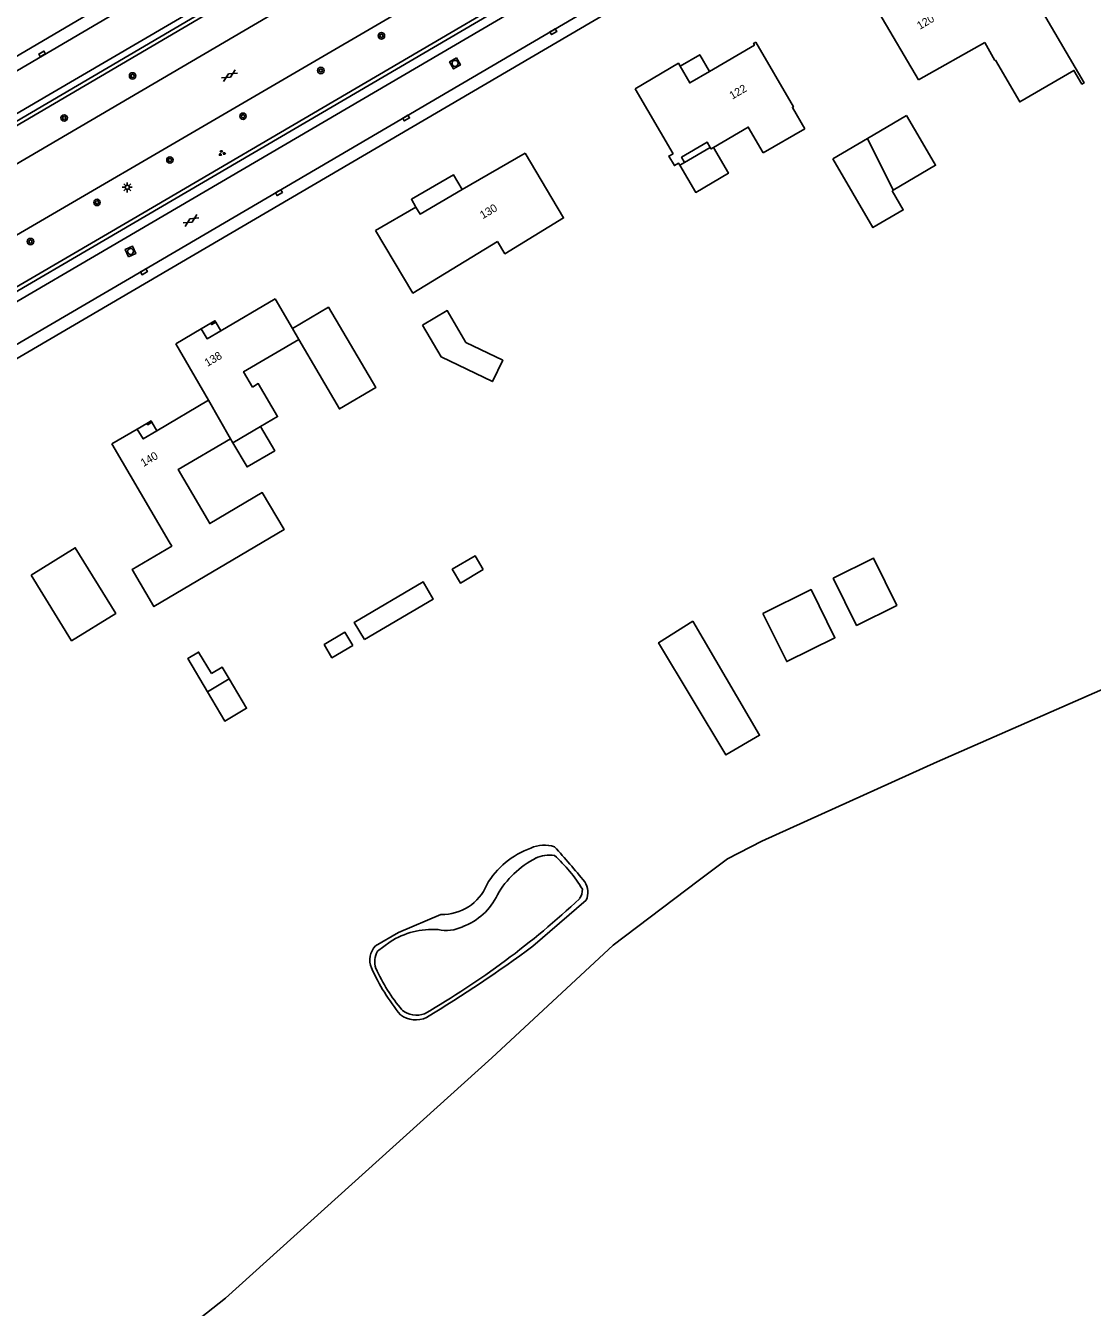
# Model space of a CAD drawing. Extents: x 135999 to 138000, y 396000 to 398501.
# Drawn here: x 136187.2 to 136320.6, y 397354.4 to 397514.6 of the extents above; entities that cross this region are included whole.
import ezdxf

# ---------------------------------------------------------------- set-up
doc = ezdxf.new("R2010")
doc.units = 0
for name, color, linetype in [('gg-afsc-draadraster', 7, 'Continuous'), ('gg-afsc-lijn draadraster', 7, 'Continuous'), ('gg-anno-huisnummerreeks BGT', 7, 'Continuous'), ('gg-bbg-bijgebouw', 7, 'Continuous'), ('gg-bbg-gedigitaliseerde bebouwing', 7, 'Continuous'), ('gg-bbg-gedigitaliseerde bebouwing onder overbouw', 7, 'Continuous'), ('gg-bbg-gedigitaliseerde bijgebouw', 7, 'Continuous'), ('gg-bbg-gedigitaliseerde overbouw', 7, 'Continuous'), ('gg-bbg-hoofdgebouw', 7, 'Continuous'), ('gg-bbg-luifel en loopbrug', 7, 'Continuous'), ('gg-bbg-onder overbouw', 7, 'Continuous'), ('gg-bbg-pand overbouw', 7, 'Continuous'), ('gg-bbg-pilaar onder overbouw', 7, 'Continuous'), ('gg-bbg-pilaar pand', 7, 'Continuous'), ('gg-bbg-tussenscheiding', 7, 'Continuous'), ('gg-knt-bronhoudergrens', 7, 'Continuous'), ('gg-knt-verharding', 7, 'Continuous'), ('gg-kntw-bovenkant insteek waterloop', 7, 'Continuous'), ('gg-kntw-waterlijn', 7, 'Continuous'), ('gt-grn-groengrens', 7, 'Continuous'), ('gt-symb-boom', 7, 'Continuous'), ('gt-symb-gesloten verharding', 7, 'Continuous'), ('gt-symb-groenvak', 7, 'Continuous'), ('gt-symb-kolk', 7, 'Continuous'), ('gt-symb-lichtmast', 7, 'Continuous'), ('gt-symb-rioolschacht', 7, 'Continuous')]:
    doc.layers.add(name, color=color, linetype=linetype)

# ---------------------------------------------------------------- blocks, each defined once
blk = doc.blocks.new('gt0-KOLK')
at = {"layer": 'gt-symb-kolk'}
blk.add_lwpolyline([(0, 0), (0.38, 0), (0.38, 0.4), (-0.38, 0.4), (-0.38, 0), (0, 0)], dxfattribs=at)
blk = doc.blocks.new('gt0-BOOM')
at = {"layer": 'gt-symb-boom'}
for radius in [0.4, 0.2]:
    blk.add_circle((0, 0), radius, dxfattribs=at)
blk = doc.blocks.new('gt0-GESVH1')
at = {"layer": 'gt-symb-gesloten verharding'}
for p, q in [((-0.99, -0.26), (0.01, 0.24)), ((0.01, -0.26), (-0.99, 0.24)), ((0.01, 0.24), (1.01, -0.26)), ((1.01, 0.24), (0.01, -0.26))]:
    blk.add_line(p, q, dxfattribs=at)
blk = doc.blocks.new('gt0-RS')
at = {"layer": 'gt-symb-rioolschacht'}
blk.add_lwpolyline([(-0.5, -0.5), (0.5, -0.5), (0.5, 0.5), (-0.5, 0.5)], close=True, dxfattribs=at)
blk.add_circle((0, 0), 0.375, dxfattribs=at)
blk = doc.blocks.new('gt0-GRVAK')
at = {"layer": 'gt-symb-groenvak'}
for p, q in [((-0.11, 0.19), (-0.23, 0.24)), ((-0.18, 0.15), (0.09, 0.15)), ((-0.09, 0.21), (-0.16, 0.32)), ((-0.05, 0.21), (-0.05, 0.39)), ((0, 0.21), (0.06, 0.32)), ((0.02, 0.19), (0.13, 0.24)), ((0.26, -0.05), (0.2, 0.06)), ((0.3, -0.05), (0.3, 0.13)), ((0.35, -0.05), (0.41, 0.06)), ((-0.24, -0.23), (-0.36, -0.18)), ((-0.32, -0.26), (-0.05, -0.26)), ((-0.23, -0.21), (-0.29, -0.1)), ((-0.18, -0.2), (-0.18, -0.02)), ((-0.14, -0.21), (-0.07, -0.1)), ((-0.12, -0.23), (0, -0.18)), ((0.24, -0.07), (0.12, -0.02)), ((0.17, -0.11), (0.44, -0.11)), ((0.37, -0.07), (0.49, -0.02))]:
    blk.add_line(p, q, dxfattribs=at)
blk = doc.blocks.new('gt0-LMAST')
at = {"layer": 'gt-symb-lichtmast'}
for p, q in [((-0.18, 0.17), (-0.45, 0.44)), ((-0.01, 0.25), (-0.01, 0.62)), ((0.17, 0.17), (0.44, 0.44)), ((-0.26, 0), (-0.63, 0)), ((-0.18, -0.18), (-0.45, -0.45)), ((-0.01, -0.25), (-0.01, -0.63)), ((0.44, -0.45), (0.17, -0.18)), ((0.24, 0), (0.62, 0))]:
    blk.add_line(p, q, dxfattribs=at)
blk.add_circle((-0.01, 0), 0.25, dxfattribs=at)

msp = doc.modelspace()

# ---------------------------------------------------------------- linework, layer by layer
at = {"layer": 'gg-afsc-draadraster'}
msp.add_lwpolyline([(136279.27, 397412.69), (136301.19, 397422.61), (136350.04, 397444.03)], dxfattribs=at)
at = {"layer": 'gg-afsc-lijn draadraster'}
msp.add_lwpolyline([(136279.27, 397412.69), (136301.19, 397422.61), (136350.04, 397444.03)], dxfattribs=at)
at = {"layer": 'gg-bbg-bijgebouw'}
for p, q in [((136292.5, 397500.53), (136297.36, 397503.39)), ((136288.14, 397497.97), (136292.5, 397500.53))]:
    msp.add_line(p, q, dxfattribs=at)
at = {"layer": 'gg-bbg-gedigitaliseerde bebouwing'}
for p, q in [((136298.87, 397507.86), (136307.14, 397512.52)), ((136308.42, 397510.26), (136307.14, 397512.52)), ((136268.16, 397498.62), (136263.4, 397506.75)), ((136284.63, 397501.74), (136279.45, 397498.72)), ((136249.64, 397498.71), (136252.99, 397493.08)), ((136269.6, 397497.53), (136269, 397497.18)), ((136220.56, 397476.78), (136218.4, 397480.48)), ((136221.36, 397475.41), (136220.56, 397476.78)), ((136213.09, 397462.49), (136216.56, 397464.52)), ((136212.81, 397462.98), (136213.09, 397462.49)), ((136197.96, 397462.34), (136205.14, 397450.1))]:
    msp.add_line(p, q, dxfattribs=at)
for points in [[(136279.45, 397498.72), (136277.56, 397501.95), (136273.21, 397499.4)], [(136268.16, 397498.62), (136267.63, 397498.32), (136268.32, 397497.13), (136268.85, 397497.44), (136269, 397497.18)], [(136273.21, 397499.4), (136272.91, 397499.23), (136272.81, 397499.4)], [(136252.99, 397493.08), (136254.46, 397490.6), (136247.12, 397486.11), (136246.18, 397487.66)], [(136246.18, 397487.66), (136235.62, 397481.21), (136230.96, 397489.01)], [(136215.55, 397469.46), (136214.44, 397471.36), (136221.36, 397475.41)], [(136216.56, 397464.52), (136218.69, 397465.76), (136216.27, 397469.89), (136215.55, 397469.46)], [(136209.91, 397452.89), (136206.25, 397459.14), (136212.81, 397462.98)], [(136205.14, 397450.1), (136205.46, 397449.57), (136200.49, 397446.63), (136203.23, 397442.01), (136219.51, 397451.64), (136216.78, 397456.27), (136210.21, 397452.38), (136209.91, 397452.89)]]:
    msp.add_lwpolyline(points, dxfattribs=at)
at = {"layer": 'gg-bbg-gedigitaliseerde bebouwing onder overbouw'}
msp.add_lwpolyline([(136272.81, 397499.4), (136272.43, 397500.05), (136269.22, 397498.17), (136269.6, 397497.53)], dxfattribs=at)
at = {"layer": 'gg-bbg-gedigitaliseerde bijgebouw'}
for p, q in [((136297.36, 397503.39), (136299.34, 397500)), ((136295.69, 397494.08), (136295.55, 397494)), ((136209.91, 397431.37), (136212.63, 397432.98))]:
    msp.add_line(p, q, dxfattribs=at)
for points in [[(136299.34, 397500), (136300.99, 397497.18), (136295.69, 397494.08)], [(136295.55, 397494), (136296.95, 397491.6), (136293.15, 397489.38), (136288.14, 397497.97)], [(136187.87, 397445.95), (136193.39, 397449.36), (136198.44, 397441.16), (136192.92, 397437.75), (136187.87, 397445.95)], [(136288.17, 397445.58), (136293.21, 397448.08), (136296.14, 397442.15), (136291.11, 397439.66), (136288.17, 397445.58)], [(136229.55, 397437.89), (136228.28, 397440.04), (136236.9, 397445.11), (136238.17, 397442.96), (136229.55, 397437.89)], [(136279.4, 397441.15), (136285.42, 397444.13), (136288.4, 397438.11), (136282.39, 397435.13), (136279.4, 397441.15)], [(136228.09, 397437.15), (136227.11, 397438.8), (136224.52, 397437.27), (136225.49, 397435.62), (136228.09, 397437.15)], [(136212.63, 397432.98), (136214.81, 397429.3), (136212.09, 397427.7), (136209.91, 397431.37)]]:
    msp.add_lwpolyline(points, dxfattribs=at)
at = {"layer": 'gg-bbg-gedigitaliseerde overbouw'}
msp.add_line((136269.6, 397497.53), (136272.81, 397499.4), dxfattribs=at)
at = {"layer": 'gg-bbg-hoofdgebouw'}
for p, q in [((136293.9, 397516.29), (136298.87, 397507.86)), ((136241.76, 397494.13), (136249.64, 397498.71)), ((136230.96, 397489.01), (136235.99, 397491.96)), ((136211.59, 397476.49), (136218.4, 397480.48)), ((136205.96, 397474.86), (136209.15, 397476.73)), ((136210.04, 397467.8), (136205.96, 397474.86)), ((136203.59, 397463.97), (136210.04, 397467.8)), ((136197.96, 397462.34), (136201.15, 397464.21))]:
    msp.add_line(p, q, dxfattribs=at)
for points in [[(136308.27, 397519.54), (136310.28, 397516.09), (136314.17, 397518.36), (136314.39, 397517.98), (136313.68, 397517.57), (136319.57, 397507.48), (136319.29, 397507.32), (136318.29, 397509.04), (136311.52, 397505.09), (136308.49, 397510.3), (136308.42, 397510.26)], [(136272.7, 397508.91), (136278.34, 397512.21), (136278.23, 397512.4), (136278.5, 397512.56)], [(136284.63, 397501.74), (136283.08, 397504.4), (136283.22, 397504.48), (136278.5, 397512.56)], [(136263.4, 397506.75), (136268.83, 397509.92), (136269.04, 397509.56)], [(136269.04, 397509.56), (136270.24, 397507.47), (136272.7, 397508.91)], [(136235.99, 397491.96), (136236.52, 397491.08), (136241.76, 397494.13)]]:
    msp.add_lwpolyline(points, dxfattribs=at)
at = {"layer": 'gg-bbg-luifel en loopbrug'}
for points in [[(136272.7, 397508.91), (136271.49, 397510.99), (136269.04, 397509.56)], [(136269, 397497.18), (136270.99, 397493.78), (136275.09, 397496.18), (136273.21, 397499.4)], [(136235.99, 397491.96), (136235.43, 397492.93), (136240.68, 397495.99), (136241.76, 397494.13)], [(136221.36, 397475.41), (136226.43, 397466.73), (136230.98, 397469.39), (136225.05, 397479.43), (136220.56, 397476.78)], [(136236.82, 397477.2), (136239.92, 397479.01), (136242.25, 397475.03), (136246.86, 397472.81), (136245.56, 397470.13), (136239.15, 397473.22), (136236.82, 397477.2)], [(136213.09, 397462.49), (136214.88, 397459.48), (136218.33, 397461.5), (136216.56, 397464.52)], [(136244.4, 397446.64), (136241.56, 397444.96), (136240.55, 397446.68), (136243.39, 397448.36), (136244.4, 397446.64)], [(136209.91, 397431.37), (136207.46, 397435.51), (136208.82, 397436.32), (136210.41, 397433.63)], [(136210.41, 397433.63), (136211.77, 397434.43), (136212.63, 397432.98)]]:
    msp.add_lwpolyline(points, dxfattribs=at)
at = {"layer": 'gg-bbg-onder overbouw'}
for points in [[(136211.59, 397476.49), (136209.88, 397475.49), (136209.15, 397476.73)], [(136203.59, 397463.97), (136201.88, 397462.97), (136201.15, 397464.21)]]:
    msp.add_lwpolyline(points, dxfattribs=at)
at = {"layer": 'gg-bbg-pand overbouw'}
for p, q in [((136209.15, 397476.73), (136210.35, 397477.44)), ((136210.96, 397477.57), (136211.59, 397476.49)), ((136201.15, 397464.21), (136202.35, 397464.92)), ((136202.96, 397465.05), (136203.59, 397463.97))]:
    msp.add_line(p, q, dxfattribs=at)
at = {"layer": 'gg-bbg-pilaar onder overbouw'}
for points in [[(136210.96, 397477.57), (136210.45, 397477.27), (136210.35, 397477.44)], [(136202.96, 397465.05), (136202.45, 397464.75), (136202.35, 397464.92)]]:
    msp.add_lwpolyline(points, dxfattribs=at)
at = {"layer": 'gg-bbg-pilaar pand'}
for points in [[(136210.35, 397477.44), (136210.86, 397477.74), (136210.96, 397477.57)], [(136202.35, 397464.92), (136202.86, 397465.22), (136202.96, 397465.05)]]:
    msp.add_lwpolyline(points, dxfattribs=at)
at = {"layer": 'gg-bbg-tussenscheiding'}
for p, q in [((136292.5, 397500.53), (136295.69, 397494.08)), ((136210.04, 397467.8), (136212.81, 397462.98))]:
    msp.add_line(p, q, dxfattribs=at)
at = {"layer": 'gg-knt-bronhoudergrens'}
msp.add_lwpolyline([(136124.38, 397299.84), (136151.7, 397314.28), (136182.19, 397331.94), (136212.18, 397355.58), (136245.51, 397385.61), (136260.68, 397399.7), (136271.32, 397407.73), (136274.95, 397410.47), (136279.27, 397412.69)], dxfattribs=at)
at = {"layer": 'gg-knt-verharding'}
for points in [[(136154.43, 397490.43), (136206.35, 397520.89), (136227.04, 397533), (136240.35, 397540.82), (136259.46, 397552.07), (136276.59, 397562.11), (136287.32, 397568.41), (136289.03, 397569.4)], [(136289.47, 397564.17), (136255.15, 397544.03), (136190.06, 397506), (136159.32, 397487.99), (136158.49, 397487.49)], [(136161.34, 397482.9), (136241.87, 397530.06), (136295.03, 397560.71), (136295.87, 397561.3)], [(136091.55, 397433.29), (136157.18, 397471.63), (136241.16, 397520.6), (136300.13, 397555.2)], [(136302.91, 397548.5), (136285.12, 397538.12), (136201.43, 397489.11), (136159.77, 397464.79), (136128.65, 397446.57)], [(136130.94, 397442.57), (136166.67, 397463.47), (136201.88, 397484.04), (136272.38, 397525.34), (136305.21, 397544.51)], [(136307.8, 397544.23), (136276.31, 397525.85), (136176.45, 397467.39), (136090.68, 397416.98)], [(136196.49, 397516.94), (136168.4, 397500.43), (136153.05, 397491.42), (136148.38, 397488.72)]]:
    msp.add_lwpolyline(points, dxfattribs=at)
at = {"layer": 'gg-kntw-bovenkant insteek waterloop'}
msp.add_line((136257.3, 397405.31), (136250.6, 397399.55), dxfattribs=at)
for points in [[(136270.65, 397440.21), (136278.99, 397425.93), (136274.77, 397423.47), (136266.34, 397437.49), (136270.65, 397440.21)], [(136239.12, 397403.54), (136233.81, 397401.27), (136230.95, 397399.59)]]:
    msp.add_lwpolyline(points, dxfattribs=at)
for centre, radius, start, end in [((136253.86, 397401.99), 10.43, 109.5588, 149.7514), ((136252.07, 397408.19), 4.01, 71.6344, 115.1574), ((136179.57, 397344.59), 99.92, 39.1039, 42.4171), ((136239.3, 397409.55), 6.02, 268.35, 337.4655), ((136255.16, 397406.3), 2.35, 335.1986, 34.2177), ((136232.72, 397397.84), 2.49, 135.3029, 203.3769), ((136149.93, 397535.52), 169.18, 301.1038, 306.517), ((136253.64, 397407.18), 25.4, 203.9869, 219.5959), ((136235.98, 397393.56), 3.2, 233.4588, 294.9526)]:
    msp.add_arc(centre, radius, start, end, dxfattribs=at)
at = {"layer": 'gg-kntw-waterlijn'}
msp.add_line((136232.76, 397400.13), (136231.21, 397398.94), dxfattribs=at)
for centre, radius, start, end in [((136256.71, 397399.77), 12.23, 117.9697, 149.3875), ((136252.74, 397406.61), 4.34, 82.3473, 114.1108), ((136239.66, 397396.01), 20.22, 31.8934, 47.485), ((136183.67, 397483.36), 106.59, 300.0771, 313.0777), ((136239.18, 397409.25), 7.72, 290.2553, 335.1052), ((136254.77, 397406.67), 2.05, 325.6956, 0.7462), ((136239.77, 397406.33), 4.8, 257.7753, 295.7045), ((136238.05, 397391.82), 9.84, 85.8731, 122.5004), ((136233.33, 397397.64), 2.49, 148.4814, 199.854), ((136251.07, 397405.73), 21.97, 203.9792, 220.0592), ((136236.06, 397393.74), 2.81, 230.0276, 291.4609)]:
    msp.add_arc(centre, radius, start, end, dxfattribs=at)
at = {"layer": 'gt-grn-groengrens'}
for points in [[(136289.46, 397563.39), (136289.71, 397562.96), (136162.46, 397488.32), (136162.21, 397488.75)], [(136289.46, 397563.39), (136181.39, 397500), (136162.21, 397488.75)], [(136301.08, 397549.28), (136284.32, 397539.51), (136200.63, 397490.5), (136158.97, 397466.18), (136127.84, 397447.95)], [(136301.08, 397549.28), (136301.33, 397548.85), (136284.57, 397539.07), (136200.88, 397490.07), (136159.22, 397465.74), (136128.09, 397447.52)]]:
    msp.add_lwpolyline(points, dxfattribs=at)

# ---------------------------------------------------------------- block references
at = {"layer": 'gt-symb-boom'}
for p in [(136231.68, 397513.36), (136224.1, 397509.02), (136200.55, 397508.35), (136192, 397503.09), (136214.37, 397503.31), (136205.22, 397497.84), (136196.11, 397492.53), (136187.79, 397487.64)]:
    msp.add_blockref('gt0-BOOM', p, dxfattribs=at)
at = {"layer": 'gt-symb-gesloten verharding'}
for p, rotation in [((136212.66, 397508.39), 30.924459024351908), ((136207.87, 397490.28), -148.12218352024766)]:
    msp.add_blockref('gt0-GESVH1', p, dxfattribs=dict(at, rotation=rotation))
at = {"layer": 'gt-symb-groenvak'}
msp.add_blockref('gt0-GRVAK', (136211.71, 397498.69), dxfattribs=at)
at = {"layer": 'gt-symb-kolk'}
for p, rotation in [((136253.09, 397514.04), -149.61576270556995), ((136189.35, 397510.92), 30.413230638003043), ((136234.67, 397503.25), -149.66519417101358), ((136218.76, 397493.93), -149.61576270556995), ((136201.88, 397484.04), -149.66519417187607)]:
    msp.add_blockref('gt0-KOLK', p, dxfattribs=dict(at, rotation=rotation))
at = {"layer": 'gt-symb-lichtmast'}
msp.add_blockref('gt0-LMAST', (136199.9, 397494.42), dxfattribs=at)
at = {"layer": 'gt-symb-rioolschacht'}
for p, rotation in [((136240.89, 397509.91), -150.33328479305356), ((136200.3, 397486.4), 23.898477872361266)]:
    msp.add_blockref('gt0-RS', p, dxfattribs=dict(at, rotation=rotation))

# ---------------------------------------------------------------- texts
at = {"layer": 'gg-anno-huisnummerreeks BGT'}
for s, rotation, p in [('120', 30.7, (136299.03, 397514.1)), ('122', 30.3, (136275.56, 397505.37)), ('130', 30.2, (136244.36, 397490.43)), ('138', 30.4, (136209.92, 397471.97)), ('140', 30.4, (136201.92, 397459.45))]:
    msp.add_text(s, height=1, rotation=rotation, dxfattribs=at).set_placement(p)

doc.saveas('drawing.dxf')
